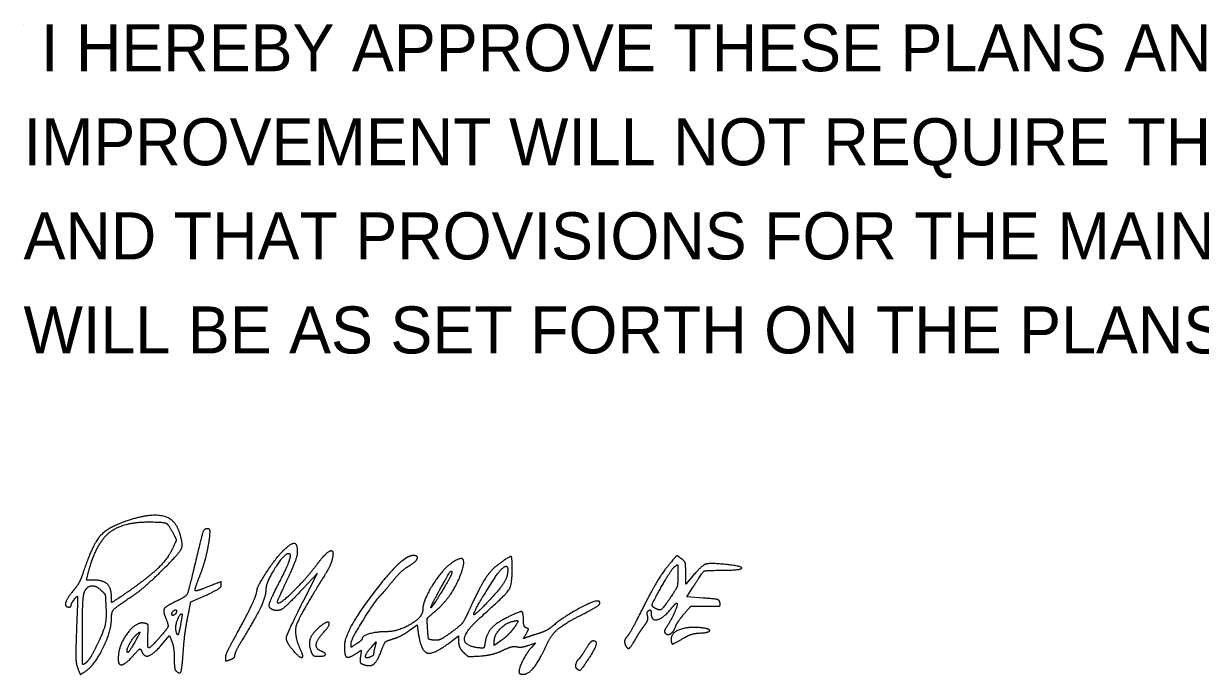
# Model space of a CAD drawing. Extents: x 0 to 34, y 0 to 22.
# Drawn here: x 24.528 to 28.033, y 8.939 to 10.877 of the extents above; entities that cross this region are included whole.
import ezdxf

# ---------------------------------------------------------------- set-up
doc = ezdxf.new("R2010")
doc.units = 0
doc.layers.add('SH_Data', color=7, linetype='Continuous')
doc.layers.add('SH_Text', color=7, linetype='Continuous')

msp = doc.modelspace()

# ---------------------------------------------------------------- linework, layer by layer
at = {"layer": 'SH_Data'}
msp.add_line((24.5279, 10.875), (24.5279, 10.875), dxfattribs=at)
msp.add_line((24.5279, 10.875), (24.5279, 10.875), dxfattribs=at)
at = {"layer": 'SH_Text'}
for p, q in [((25.3839, 9.0082), (25.3839, 9.0082)), ((25.1298, 8.9903), (25.1298, 8.9903)), ((26.1747, 8.9573), (26.1747, 8.9573))]:
    msp.add_line(p, q, dxfattribs=at)
for points in [[(25.3624, 9.1605), (25.4028, 9.2412), (25.3588, 9.1936)], [(26.522, 9.234), (26.4998, 9.2081), (26.4998, 9.2412)], [(26.5512, 9.1666), (26.5026, 9.17), (26.5218, 9.2)], [(25.0169, 9.1094), (25.0265, 9.1555), (25.0715, 9.1754)], [(25.6766, 9.0701), (25.6998, 9.0873), (25.7018, 9.072)], [(24.9391, 9.0276), (24.9628, 9.0552), (24.9696, 9.0372)], [(25.8015, 9.0375), (25.8232, 9.054), (25.8232, 9.037)], [(25.5637, 9.0209), (25.5775, 9.0366), (25.5738, 9.02)], [(25.9495, 9.0398), (25.9298, 9.0257), (25.9298, 9.0394)], [(26.0309, 9.026), (26.0523, 9.0335), (26.0391, 9.0184)]]:
    msp.add_lwpolyline(points, dxfattribs=at)
for points in [[(24.8329, 9.3955), (24.7758, 9.376), (24.7306, 9.3206), (24.7031, 9.2362)], [(24.7194, 9.2374), (24.7414, 9.3251), (24.8197, 9.3933), (24.8985, 9.3933)], [(24.9918, 9.364), (24.9786, 9.4037), (24.9017, 9.419), (24.8329, 9.3955)], [(24.8985, 9.3933), (24.9444, 9.3933), (24.9594, 9.3865), (24.9733, 9.3596)], [(24.9376, 9.2465), (24.9919, 9.3), (25.0042, 9.3267), (24.9918, 9.364)], [(24.9733, 9.3596), (24.9828, 9.3414), (24.9826, 9.3375), (24.972, 9.3148)], [(25.0748, 9.3733), (25.0657, 9.3733), (25.0578, 9.3508), (25.0395, 9.2733)], [(25.0524, 9.2313), (25.066, 9.266), (25.0832, 9.3409), (25.0832, 9.3655)], [(25.0832, 9.3655), (25.0832, 9.3698), (25.0794, 9.3733), (25.0748, 9.3733)], [(25.3023, 9.3092), (25.3255, 9.3313), (25.3432, 9.3288), (25.3432, 9.3034)], [(24.972, 9.3148), (24.9586, 9.2864), (24.9104, 9.2371), (24.8606, 9.2009)], [(25.2232, 9.1907), (25.2232, 9.201), (25.2832, 9.291), (25.3023, 9.3092)], [(25.3142, 9.2983), (25.3003, 9.294), (25.2498, 9.2125), (25.2498, 9.1944)], [(25.2876, 9.2095), (25.3147, 9.2618), (25.3268, 9.3021), (25.3142, 9.2983)], [(25.3432, 9.3034), (25.3432, 9.294), (25.3297, 9.2575), (25.3132, 9.2222)], [(25.4052, 9.2712), (25.4304, 9.3047), (25.4539, 9.3106), (25.4467, 9.2816)], [(25.6877, 9.2933), (25.6543, 9.2933), (25.4832, 9.0676), (25.4832, 9.0235)], [(25.6744, 9.2616), (25.6964, 9.2746), (25.7043, 9.2933), (25.6877, 9.2933)], [(25.9832, 9.2554), (25.9832, 9.2897), (25.976, 9.2919), (25.9433, 9.2678)], [(26.4865, 9.2842), (26.4742, 9.2933), (26.4717, 9.2924), (26.4546, 9.272)], [(25.0395, 9.2733), (25.0187, 9.1849), (25.0121, 9.1713), (24.9824, 9.157)], [(25.2832, 9.1557), (25.2832, 9.141), (25.3667, 9.2201), (25.4052, 9.2712)], [(25.4467, 9.2816), (25.4443, 9.2715), (25.4339, 9.2498), (25.4236, 9.2333)], [(25.6261, 9.2159), (25.6405, 9.2338), (25.6622, 9.2544), (25.6744, 9.2616)], [(25.8029, 9.2712), (25.7737, 9.2508), (25.7165, 9.1576), (25.7165, 9.1307)], [(25.7461, 9.1209), (25.8029, 9.1655), (25.8571, 9.3092), (25.8029, 9.2712)], [(25.9433, 9.2678), (25.9195, 9.2502), (25.8867, 9.2001), (25.8575, 9.1366)], [(25.8904, 9.111), (25.9641, 9.1768), (25.9832, 9.2065), (25.9832, 9.2554)], [(25.926, 9.2192), (25.9448, 9.249), (25.9698, 9.2671), (25.9698, 9.251)], [(26.4546, 9.272), (26.4319, 9.245), (26.3931, 9.18), (26.3599, 9.1133)], [(26.4261, 9.1979), (26.4427, 9.2274), (26.4608, 9.2552), (26.4664, 9.2599)], [(26.4664, 9.2599), (26.4752, 9.2672), (26.4765, 9.264), (26.4765, 9.2349)], [(26.4998, 9.2412), (26.4998, 9.2666), (26.4967, 9.2767), (26.4865, 9.2842)], [(26.6182, 9.2668), (26.5705, 9.2716), (26.5475, 9.2638), (26.522, 9.234)], [(26.6104, 9.2496), (26.6641, 9.25), (26.6693, 9.2615), (26.6182, 9.2668)], [(24.7031, 9.2362), (24.6984, 9.2218), (24.686, 9.2001), (24.6755, 9.1881)], [(24.7386, 9.22), (24.7165, 9.22), (24.7153, 9.2211), (24.7194, 9.2374)], [(24.7898, 9.1689), (24.7898, 9.1958), (24.7656, 9.22), (24.7386, 9.22)], [(24.8532, 9.1737), (24.8715, 9.1861), (24.9095, 9.2188), (24.9376, 9.2465)], [(25.039, 9.1886), (25.0377, 9.1899), (25.0437, 9.2091), (25.0524, 9.2313)], [(25.3132, 9.2222), (25.2967, 9.1869), (25.2832, 9.1569), (25.2832, 9.1557)], [(25.4236, 9.2333), (25.3496, 9.1139), (25.3314, 9.0597), (25.3509, 9.0169)], [(25.763, 9.1833), (25.7898, 9.2321), (25.8032, 9.2518), (25.8032, 9.2427)], [(25.8032, 9.2427), (25.8032, 9.2389), (25.7925, 9.218), (25.7794, 9.1962)], [(25.9295, 9.1759), (25.869, 9.1096), (25.8676, 9.1267), (25.926, 9.2192)], [(25.9698, 9.251), (25.9698, 9.233), (25.9531, 9.2018), (25.9295, 9.1759)], [(26.4765, 9.2349), (26.4765, 9.2083), (26.4721, 9.1949), (26.4548, 9.1691)], [(26.5218, 9.2), (26.5503, 9.2447), (26.5583, 9.2492), (26.6104, 9.2496)], [(24.6755, 9.1881), (24.6569, 9.1666), (24.65, 9.14), (24.6632, 9.14)], [(24.7032, 9.0696), (24.7032, 9.1289), (24.7061, 9.1797), (24.7101, 9.1871)], [(24.7101, 9.1871), (24.7184, 9.2027), (24.7449, 9.204), (24.7594, 9.1895)], [(24.7594, 9.1895), (24.7716, 9.1773), (24.7711, 9.1787), (24.7733, 9.14)], [(24.8606, 9.2009), (24.8418, 9.1873), (24.8182, 9.171), (24.8082, 9.1646)], [(25.0759, 9.1997), (25.0569, 9.1922), (25.0403, 9.1872), (25.039, 9.1886)], [(25.0715, 9.1754), (25.0962, 9.1863), (25.1165, 9.1993), (25.1165, 9.2043)], [(25.1165, 9.2043), (25.1165, 9.2158), (25.1167, 9.2158), (25.0759, 9.1997)], [(25.151, 9.0387), (25.1874, 9.1039), (25.2232, 9.1793), (25.2232, 9.1907)], [(25.2498, 9.1944), (25.2498, 9.1734), (25.2229, 9.1145), (25.1842, 9.0508)], [(25.2715, 9.1314), (25.2573, 9.1365), (25.2622, 9.1606), (25.2876, 9.2095)], [(25.3588, 9.1936), (25.3143, 9.1456), (25.2868, 9.126), (25.2715, 9.1314)], [(25.5959, 9.18), (25.598, 9.1818), (25.6116, 9.198), (25.6261, 9.2159)], [(25.7794, 9.1962), (25.7473, 9.1427), (25.7356, 9.1335), (25.763, 9.1833)], [(26.4046, 9.1388), (26.3981, 9.143), (26.4033, 9.1572), (26.4261, 9.1979)], [(24.6698, 9.1453), (24.6698, 9.1483), (24.6743, 9.1566), (24.6798, 9.1637)], [(24.6798, 9.1637), (24.6886, 9.1753), (24.6893, 9.166), (24.6857, 9.0766)], [(24.7898, 9.1071), (24.7898, 9.126), (24.8031, 9.1401), (24.8532, 9.1737)], [(24.8082, 9.1646), (24.79, 9.1531), (24.7898, 9.1532), (24.7898, 9.1689)], [(24.9824, 9.157), (24.9516, 9.1421), (24.9426, 9.1289), (24.9502, 9.11)], [(25.3319, 9.0095), (25.3082, 9.037), (25.3134, 9.0629), (25.3624, 9.1605)], [(25.5032, 9.0329), (25.5032, 9.0437), (25.5814, 9.1679), (25.5959, 9.18)], [(26.2422, 9.1565), (26.2349, 9.1638), (26.1353, 9.1105), (26.0998, 9.0803)], [(26.1865, 9.1153), (26.2281, 9.1364), (26.2477, 9.1509), (26.2422, 9.1565)], [(26.4548, 9.1691), (26.4329, 9.1364), (26.4202, 9.1288), (26.4046, 9.1388)], [(26.474, 9.1513), (26.477, 9.1483), (26.4536, 9.096), (26.4415, 9.0786)], [(26.4588, 9.138), (26.4657, 9.1468), (26.4725, 9.1528), (26.474, 9.1513)], [(26.6017, 9.1527), (26.6002, 9.1608), (26.5885, 9.1641), (26.5512, 9.1666)], [(26.5594, 9.1427), (26.5966, 9.1421), (26.6034, 9.1438), (26.6017, 9.1527)], [(24.6632, 9.14), (24.6668, 9.14), (24.6698, 9.1424), (24.6698, 9.1453)], [(24.7733, 9.14), (24.7753, 9.1043), (24.7641, 9.0613), (24.7411, 9.0157)], [(24.9698, 9.1192), (24.9698, 9.1228), (24.9728, 9.1277), (24.9765, 9.13)], [(24.9765, 9.1166), (24.9728, 9.1144), (24.9698, 9.1155), (24.9698, 9.1192)], [(24.9765, 9.13), (24.9802, 9.1322), (24.9832, 9.1311), (24.9832, 9.1274)], [(24.9832, 9.1274), (24.9832, 9.1237), (24.9802, 9.1189), (24.9765, 9.1166)], [(24.9816, 9.0711), (24.9792, 9.0817), (24.9929, 9.12), (24.9991, 9.12)], [(24.9991, 9.12), (25.0004, 9.12), (24.9992, 9.1078), (24.9964, 9.093)], [(25.7165, 9.1307), (25.7165, 9.1099), (25.6436, 9.0666), (25.6085, 9.0666)], [(25.7311, 9.0754), (25.7293, 9.1031), (25.7314, 9.1092), (25.7461, 9.1209)], [(25.8575, 9.1366), (25.8403, 9.0995), (25.829, 9.0848), (25.8016, 9.0646)], [(26.0165, 9.1), (26.0165, 9.1255), (26.0056, 9.1276), (25.9686, 9.1091)], [(26.0842, 9.0247), (26.0984, 9.0561), (26.1367, 9.09), (26.1865, 9.1153)], [(26.3599, 9.1133), (26.3462, 9.0858), (26.3305, 9.0582), (26.3249, 9.0519)], [(26.3773, 9.0859), (26.3843, 9.0948), (26.3884, 9.1073), (26.3863, 9.1138)], [(26.3863, 9.1138), (26.3843, 9.1202), (26.3857, 9.1274), (26.3896, 9.1298)], [(26.3896, 9.1298), (26.3934, 9.1321), (26.3965, 9.1293), (26.3965, 9.1235)], [(26.3965, 9.1235), (26.3965, 9.0981), (26.4343, 9.1069), (26.4588, 9.138)], [(26.4694, 9.0815), (26.4727, 9.0898), (26.4843, 9.1071), (26.4952, 9.12)], [(26.4952, 9.12), (26.5144, 9.1425), (26.5167, 9.1433), (26.5594, 9.1427)], [(24.7116, 8.9484), (24.7395, 8.9669), (24.7898, 9.069), (24.7898, 9.1071)], [(24.8875, 9.092), (24.8629, 9.097), (24.8098, 9.0245), (24.8098, 8.9858)], [(24.8982, 9.058), (24.8995, 9.084), (24.8977, 9.0899), (24.8875, 9.092)], [(24.9502, 9.11), (24.9596, 9.0867), (24.957, 9.0771), (24.9348, 9.0515)], [(24.9964, 9.093), (24.9907, 9.0617), (24.9855, 9.0539), (24.9816, 9.0711)], [(25.0036, 9.0072), (25.0057, 9.038), (25.0117, 9.084), (25.0169, 9.1094)], [(25.4073, 9.0787), (25.3865, 9.0606), (25.3761, 9.0293), (25.3839, 9.0082)], [(25.4203, 9.0632), (25.4427, 9.0874), (25.4319, 9.1003), (25.4073, 9.0787)], [(25.8832, 9.0185), (25.8393, 9.0235), (25.8428, 9.0685), (25.8904, 9.111)], [(25.9686, 9.1091), (25.9343, 9.092), (25.9057, 9.0593), (25.9021, 9.0333)], [(25.9298, 9.0394), (25.9298, 9.0562), (25.961, 9.0907), (25.9815, 9.0966)], [(25.9815, 9.0966), (26.0001, 9.1019), (26.0006, 9.0936), (25.9829, 9.0711)], [(26.0248, 9.0781), (26.0202, 9.0797), (26.0165, 9.0896), (26.0165, 9.1)], [(26.0243, 9.0601), (26.0313, 9.0719), (26.0314, 9.0757), (26.0248, 9.0781)], [(26.0998, 9.0803), (26.0925, 9.074), (26.0745, 9.0652), (26.0598, 9.0607)], [(26.3519, 9.0469), (26.3589, 9.0594), (26.3703, 9.077), (26.3773, 9.0859)], [(26.4415, 9.0786), (26.4372, 9.0724), (26.4356, 9.0652), (26.4381, 9.0628)], [(26.4381, 9.0628), (26.4457, 9.0552), (26.4631, 9.0655), (26.4694, 9.0815)], [(26.5404, 9.0788), (26.5048, 9.0817), (26.4565, 9.0628), (26.4565, 9.0461)], [(26.5392, 9.0624), (26.5707, 9.0637), (26.5716, 9.0762), (26.5404, 9.0788)], [(24.6857, 9.0766), (24.683, 9.0092), (24.6842, 8.9704), (24.6892, 8.9576)], [(24.7137, 8.9737), (24.7042, 8.9658), (24.7032, 8.9751), (24.7032, 9.0696)], [(24.8365, 9.009), (24.8365, 9.0185), (24.8557, 9.051), (24.8667, 9.0601)], [(24.8632, 9.043), (24.8476, 9.0149), (24.8365, 9.0007), (24.8365, 9.009)], [(24.8667, 9.0601), (24.875, 9.067), (24.8741, 9.0628), (24.8632, 9.043)], [(24.9348, 9.0515), (24.9053, 9.0174), (24.8962, 9.0191), (24.8982, 9.058)], [(25.1842, 9.0508), (25.169, 9.0258), (25.1565, 9.0014), (25.1565, 8.9967)], [(25.4132, 9.009), (25.3977, 9.015), (25.4013, 9.0427), (25.4203, 9.0632)], [(25.5365, 9.0471), (25.5365, 9.044), (25.529, 9.0366), (25.5198, 9.0306)], [(25.6085, 9.0666), (25.5809, 9.0665), (25.5365, 9.0545), (25.5365, 9.0471)], [(25.593, 9.0086), (25.6024, 9.0332), (25.6085, 9.0394), (25.6288, 9.0455)], [(25.6288, 9.0455), (25.6423, 9.0496), (25.6638, 9.0606), (25.6766, 9.0701)], [(25.7018, 9.072), (25.7098, 9.0098), (25.7479, 8.9967), (25.8015, 9.0375)], [(25.7502, 9.0413), (25.7349, 9.0431), (25.733, 9.0466), (25.7311, 9.0754)], [(25.8016, 9.0646), (25.7786, 9.0477), (25.7616, 9.04), (25.7502, 9.0413)], [(25.9829, 9.0711), (25.9754, 9.0616), (25.9604, 9.0475), (25.9495, 9.0398)], [(26.0243, 9.0488), (26.017, 9.0458), (26.017, 9.0477), (26.0243, 9.0601)], [(26.0598, 9.0607), (26.0452, 9.0561), (26.0292, 9.0508), (26.0243, 9.0488)], [(26.3249, 9.0519), (26.3194, 9.0456), (26.3167, 9.0356), (26.319, 9.0297)], [(26.319, 9.0297), (26.325, 9.0142), (26.3372, 9.0207), (26.3519, 9.0469)], [(26.4565, 9.0461), (26.4565, 9.0297), (26.4635, 9.03), (26.493, 9.0474)], [(26.493, 9.0474), (26.5062, 9.0552), (26.527, 9.062), (26.5392, 9.0624)], [(24.7411, 9.0157), (24.7318, 8.9974), (24.7195, 8.9785), (24.7137, 8.9737)], [(24.8552, 8.9962), (24.8701, 9.0132), (24.8763, 9.0166), (24.8791, 9.0096)], [(24.8791, 9.0096), (24.8864, 8.9905), (24.9146, 8.999), (24.9391, 9.0276)], [(24.9696, 9.0372), (24.9734, 9.0272), (24.9765, 9.0048), (24.9765, 8.9873)], [(24.9811, 8.9509), (24.9933, 8.9387), (25.0002, 8.9559), (25.0036, 9.0072)], [(25.1298, 8.9903), (25.1298, 8.996), (25.1394, 9.0178), (25.151, 9.0387)], [(25.3509, 9.0169), (25.3624, 8.9916), (25.3511, 8.9872), (25.3319, 9.0095)], [(25.3839, 9.0082), (25.3876, 8.9981), (25.3949, 8.9933), (25.4063, 8.9933)], [(25.4063, 8.9933), (25.4248, 8.9933), (25.429, 9.003), (25.4132, 9.009)], [(25.4832, 9.0235), (25.4832, 8.9952), (25.4962, 8.9872), (25.5186, 9.0019)], [(25.5198, 9.0306), (25.504, 9.0202), (25.5032, 9.0203), (25.5032, 9.0329)], [(25.5186, 9.0019), (25.5336, 9.0117), (25.5339, 9.0114), (25.5312, 8.9927)], [(25.5395, 8.9692), (25.5593, 8.9616), (25.5812, 8.9777), (25.593, 9.0086)], [(25.5598, 8.9909), (25.5452, 8.9853), (25.5474, 9.0024), (25.5637, 9.0209)], [(25.5738, 9.02), (25.5717, 9.0108), (25.57, 9.0014), (25.5699, 8.999)], [(25.8232, 9.037), (25.8232, 9.0276), (25.8295, 9.0136), (25.8372, 9.0059)], [(25.9021, 9.0333), (25.9002, 9.0199), (25.8965, 9.017), (25.8832, 9.0185)], [(25.8893, 8.9945), (25.9102, 8.9961), (25.94, 9.0036), (25.9555, 9.0113)], [(25.9555, 9.0113), (25.971, 9.0189), (25.9895, 9.0237), (25.9966, 9.0219)], [(25.9966, 9.0219), (26.0036, 9.02), (26.0191, 9.0219), (26.0309, 9.026)], [(26.0391, 9.0184), (26.0256, 9.0029), (26.0032, 8.958), (26.0032, 8.9464)], [(26.0165, 8.94), (26.0315, 8.94), (26.0646, 8.9814), (26.0842, 9.0247)], [(26.183, 8.9866), (26.1853, 8.9885), (26.194, 9.0012), (26.2024, 9.015)], [(26.2024, 9.015), (26.2107, 9.0287), (26.2203, 9.04), (26.2237, 9.04)], [(26.2237, 9.04), (26.2359, 9.04), (26.2294, 9.0149), (26.2092, 8.9844)], [(24.8098, 8.9858), (24.8098, 8.9656), (24.8331, 8.971), (24.8552, 8.9962)], [(24.9765, 8.9873), (24.9765, 8.9698), (24.9786, 8.9535), (24.9811, 8.9509)], [(25.146, 8.984), (25.131, 8.9783), (25.1298, 8.9787), (25.1298, 8.9903)], [(25.1565, 8.9967), (25.1565, 8.9919), (25.1518, 8.9862), (25.146, 8.984)], [(25.5312, 8.9927), (25.5292, 8.979), (25.5316, 8.9722), (25.5395, 8.9692)], [(25.5699, 8.999), (25.5699, 8.9966), (25.5653, 8.993), (25.5598, 8.9909)], [(25.8372, 9.0059), (25.8491, 8.994), (25.8573, 8.9922), (25.8893, 8.9945)], [(26.1747, 8.9573), (26.1705, 8.9615), (26.176, 8.981), (26.183, 8.9866)], [(26.2092, 8.9844), (26.1891, 8.954), (26.1829, 8.9491), (26.1747, 8.9573)], [(24.6892, 8.9576), (24.6963, 8.9396), (24.6976, 8.9391), (24.7116, 8.9484)], [(26.0032, 8.9464), (26.0032, 8.9429), (26.0091, 8.94), (26.0165, 8.94)]]:
    msp.add_open_spline(points, degree=2, dxfattribs=at)

# ---------------------------------------------------------------- texts
at = {"layer": 'SH_Data'}
for s, p in [(' I HEREBY APPROVE THESE PLANS AND DECLARE THAT THE MAKING OF THIS', (24.5279, 10.735)), ('IMPROVEMENT WILL NOT REQUIRE THE CLOSING TO TRAFFIC OF THE HIGHWAY', (24.5279, 10.455)), ('AND THAT PROVISIONS FOR THE MAINTENANCE AND SAFETY OF TRAFFIC', (24.5279, 10.175)), ('WILL BE AS SET FORTH ON THE PLANS AND ESTIMATES.', (24.5279, 9.895))]:
    msp.add_text(s, height=0.14, dxfattribs=at).set_placement(p)

doc.saveas('drawing.dxf')
